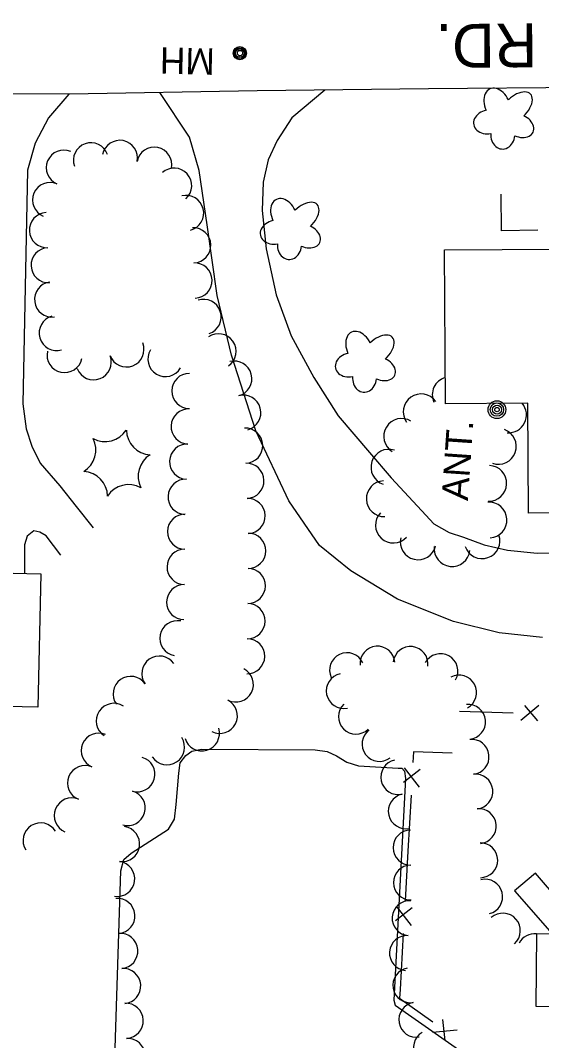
# Model space of a CAD drawing. Extents: x 189384 to 193282, y 256970 to 260388.
# Drawn here: x 190703.8 to 190822.4, y 259634.9 to 259866.8 of the extents above; entities that cross this region are included whole.
import ezdxf

# ---------------------------------------------------------------- set-up
doc = ezdxf.new("R2010")
doc.units = 0
for name, color, linetype in [('E_DRN_Grate', 7, 'Continuous'), ('E_DWY', 7, 'Continuous'), ('E_LAND_Vegetation', 7, 'Continuous'), ('E_MISCPROP', 7, 'Continuous'), ('E_MISCPROP_HvyDash', 7, 'Continuous'), ('E_MISCPROP_HvyLine', 7, 'Continuous'), ('E_MISCPROP_Railing', 7, 'Continuous'), ('E_RDWY', 7, 'Continuous'), ('E_RDWY_Name', 7, 'Continuous')]:
    doc.layers.add(name, color=color, linetype=linetype)

# ---------------------------------------------------------------- blocks, each defined once
blk = doc.blocks.new('MHO_6')
at = {"layer": 'E_DRN_Grate'}
for centre, radius in [((0.04, -0.06), 1.5), ((0.04, -0.06), 1.22), ((0.04, -0.07), 0.968), ((0.01, -0.08), 0.605)]:
    blk.add_circle(centre, radius, dxfattribs=at)
blk = doc.blocks.new('MHT_4')
at = {"layer": 'E_DRN_Grate'}
blk.add_text('MH', height=6, rotation=0, dxfattribs=at).set_placement((-5.61, -3.06))
blk = doc.blocks.new('POLE_3')
at = {"layer": 'E_MISCPROP'}
for centre, radius in [((-0.01, 0.02), 2.02), ((-0.01, 0.03), 1.52), ((0, -0.01), 1.01), ((0, 0), 0.502)]:
    blk.add_circle(centre, radius, dxfattribs=at)
blk = doc.blocks.new('ANT_2')
at = {"layer": 'E_MISCPROP'}
blk.add_text('ANT.', height=6, rotation=360, dxfattribs=at).set_placement((0.55, -0.39))
blk = doc.blocks.new('PINEL')
at = {"layer": 'E_LAND_Vegetation'}
for centre, start, end in [((-8.23, 7.26), 275.2112, 0.9761), ((2.17, 10.66), 215.2112, 300.9761), ((10.31, 3.35), 155.2112, 240.9761), ((-10.49, -3.45), 335.2112, 60.9761), ((8.05, -7.36), 95.2112, 180.9761), ((-2.35, -10.75), 35.2112, 120.9761)]:
    blk.add_arc(centre, 5.72, start, end, dxfattribs=at)
blk = doc.blocks.new('TREE')
at = {"layer": 'E_LAND_Vegetation'}
for centre, major_axis, ratio in [((-1.07, 3.38), (0.91, -3.32), 0.782863), ((2.88, 1.66), (-3.52, -1.95), 0.691916), ((-3.74, -0.07), (3.29, -0.08), 0.832022), ((2.54, -2.64), (-3.34, 3.06), 0.560249), ((-1.48, -3.66), (1.2, 3.24), 0.716896)]:
    blk.add_ellipse(centre, major_axis=major_axis, ratio=ratio, start_param=1.570796, end_param=4.712389, dxfattribs=at)

msp = doc.modelspace()

# ---------------------------------------------------------------- linework, layer by layer
at = {"layer": 'E_DWY'}
for points in [[(190714.86, 259850.07), (190710.22, 259844.68), (190707.14, 259838.94), (190705.46, 259832.74), (190704.36, 259779.68), (190705.13, 259773.97), (190706.42, 259770.05), (190708.29, 259766.17), (190712.77, 259760.97), (190716.53, 259756.29), (190720.4, 259751.42)], [(190822.67, 259726.51), (190812.77, 259727.59), (190802.36, 259730.18), (190789.63, 259735.25), (190779, 259741.66), (190771.88, 259747.4), (190764.87, 259757.58), (190757.37, 259773.48), (190751.88, 259790.71), (190748.62, 259804.27), (190746.3, 259820.32), (190744.49, 259832.67), (190742.31, 259840.27), (190735.54, 259850.42)], [(190773.11, 259850.97), (190765.59, 259844.64), (190762.27, 259839.55), (190760.24, 259835.15), (190759.04, 259830.05), (190758.81, 259823.59), (190759.74, 259814.92), (190762.06, 259804.45), (190765.45, 259795.12), (190770.57, 259785.65), (190776.12, 259776.89), (190783.26, 259768.55), (190788.17, 259762.81), (190795.15, 259755.33), (190797.89, 259752.39), (190801.43, 259750.38), (190804.69, 259749.31), (190809.35, 259747.59), (190814.65, 259746.4), (190821.43, 259745.72), (190834.6, 259745.78)], [(190713.04, 259745.23), (190709.68, 259749.65), (190708.27, 259750.49), (190706.9, 259750.76), (190705.36, 259749.58), (190704.76, 259747.6), (190704.71, 259741.1)], [(190725.28, 259630.81), (190726.64, 259673.45), (190727.36, 259676.06), (190728.99, 259677.51), (190737.49, 259682.96), (190738.9, 259685.19), (190739.27, 259688.57), (190739.84, 259695.68), (190740.15, 259698.04), (190741.46, 259699.68), (190742.84, 259700.67), (190745.05, 259701.15), (190770.92, 259701), (190773.65, 259700.58), (190775.77, 259699.59), (190778.08, 259698.18), (190780.77, 259697.32), (190789.78, 259696.77), (190790.65, 259696.77), (190791.22, 259696.09), (190791.43, 259694.43), (190788.77, 259644.03), (190789.08, 259642.89), (190819.96, 259621.32)]]:
    msp.add_lwpolyline(points, dxfattribs=at)
at = {"layer": 'E_LAND_Vegetation'}
for centre, radius, start, end in [((190713.69, 259833.34), 4, 67.007, 246.9917), ((190719.86, 259835.01), 4, 19.509, 199.4937), ((190726.44, 259835.56), 4, 348.7183, 168.703), ((190734.29, 259833.99), 4, 348.7183, 168.703), ((190738.8, 259829.24), 4, 312.0189, 132.0036), ((190710.57, 259825.98), 4, 67.007, 246.9917), ((190741.54, 259823.03), 4, 284.298, 104.2826), ((190709.86, 259819.14), 4, 92.8579, 272.8425), ((190743.16, 259815.68), 4, 272.1039, 92.0886), ((190710.25, 259811.15), 4, 92.8579, 272.8425), ((190743.45, 259807.68), 4, 272.1039, 92.0886), ((190711.04, 259803.36), 4, 97.325, 277.3097), ((190745.51, 259799.4), 4, 288.5413, 108.526), ((190712.09, 259795.76), 4, 106.1392, 286.1239), ((190748.91, 259791.58), 4, 304.8154, 124.8001), ((190727.94, 259792.02), 4, 201.3898, 21.3745), ((190713.87, 259790.76), 4, 167.9757, 347.9603), ((190736.82, 259789.85), 4, 149.1247, 329.1094), ((190720.49, 259789.1), 4, 201.3898, 21.3745), ((190752.5, 259785.37), 4, 284.7594, 104.7441), ((190742.26, 259782.56), 4, 89.4755, 269.4602), ((190801.63, 259781.71), 4.07, 106.243, 203.9106), ((190754.54, 259777.63), 4, 284.7594, 104.7441), ((190795.02, 259777.82), 4.07, 35.2422, 215.2269), ((190814.92, 259777.14), 4.07, 265.7473, 40.4027), ((190742.11, 259774.49), 4, 87.5068, 267.4915), ((190790.58, 259772.24), 4.07, 58.531, 238.5157), ((190754.97, 259770.13), 4, 271.9978, 91.9825), ((190812.6, 259769.96), 4.07, 250.5561, 70.5407), ((190741.76, 259766.5), 4, 87.5068, 267.4915), ((190787.67, 259765.24), 4.07, 71.9601, 251.9448), ((190755.25, 259762.14), 4, 271.9978, 91.9825), ((190810.41, 259761.56), 4.07, 267.5573, 87.542), ((190741.41, 259758.5), 4, 87.5068, 267.4915), ((190786.62, 259758.06), 4.07, 92.2877, 272.2724), ((190755.53, 259754.14), 4, 271.9978, 91.9825), ((190810.47, 259753.22), 4.07, 273.5045, 93.4892), ((190741.28, 259750.57), 4, 89.3282, 269.3129), ((190788.71, 259752.08), 4.07, 137.0153, 317), ((190755.66, 259746.24), 4, 269.4451, 89.4298), ((190794.35, 259748.26), 4.07, 166.6956, 346.6803), ((190808.89, 259748.52), 4.07, 199.1129, 19.0976), ((190802.06, 259746.72), 4.07, 173.5239, 353.5086), ((190741.18, 259742.57), 4, 89.3282, 269.3129), ((190755.58, 259738.24), 4, 269.4451, 89.4298), ((190741.09, 259734.57), 4, 89.3282, 269.3129), ((190755.5, 259730.24), 4, 269.4451, 89.4298), ((190739.55, 259726.34), 4, 79.0518, 259.0364), ((190755.42, 259722.24), 4, 269.4451, 89.4298), ((190785.08, 259720.57), 3.97, 4.8269, 184.8115), ((190792.6, 259720.49), 3.97, 353.2953, 173.2799), ((190735.45, 259718.3), 4, 35.295, 215.2797), ((190778.15, 259719.08), 3.97, 25.1576, 205.1423), ((190799.41, 259718.86), 3.97, 330.7842, 150.7689), ((190752.84, 259715.84), 4, 243.0063, 62.991), ((190728.92, 259713.68), 4, 35.295, 215.2797), ((190777.4, 259714.36), 3.97, 101.9581, 281.9428), ((190803.68, 259714), 3.97, 298.2652, 118.2498), ((190749.21, 259708.71), 4, 243.0063, 62.991), ((190725.08, 259707.55), 4, 56.837, 236.8217), ((190780.18, 259708.51), 3.97, 134.2601, 314.2448), ((190805.71, 259707.33), 3.97, 275.5855, 95.5702), ((190745.11, 259704.71), 4, 196.8082, 16.7929), ((190785.55, 259702.32), 3.97, 127.181, 307.1657), ((190721.65, 259700.78), 4, 67.1882, 247.1729), ((190737.18, 259701.58), 4, 213.0132, 32.9978), ((190806.51, 259699.4), 3.97, 276.2135, 96.1982), ((190730.44, 259695.42), 4, 253.908, 73.8926), ((190789.81, 259694.76), 3.97, 102.3955, 282.3802), ((190718.55, 259693.41), 4, 67.1882, 247.1729), ((190807.36, 259691.5), 3.97, 276.2135, 96.1982), ((190728.22, 259687.74), 4, 253.908, 73.8926), ((190715.49, 259686.03), 4, 67.4818, 247.4664), ((190791.52, 259687), 3.97, 102.3955, 282.3802), ((190808.15, 259683.62), 3.97, 275.5953, 95.58), ((190708.41, 259680.36), 4, 32.3111, 212.2958), ((190726.96, 259679.55), 4, 261.8375, 81.8222), ((190792.61, 259678.75), 3.97, 90.6728, 270.6575), ((190808.47, 259675.87), 3.97, 270.5674, 90.5521), ((190725.83, 259671.63), 4, 261.8375, 81.8222), ((190792.7, 259670.8), 3.97, 90.6728, 270.6575), ((190809.58, 259667.57), 3.97, 284.1445, 104.1292), ((190725.87, 259663.2), 4, 274.8332, 94.8179), ((190792.39, 259662.69), 3.97, 85.7021, 265.6868), ((190813.63, 259659.86), 3.97, 311.6972, 131.6819), ((190726.54, 259655.23), 4, 274.8332, 94.8179), ((190791.79, 259654.77), 3.97, 85.7021, 265.6868), ((190820.85, 259655.19), 3.97, 83.4113, 152.8171), ((190727.21, 259647.26), 4, 274.8332, 94.8179), ((190792.55, 259647.43), 3.97, 99.891, 279.8757), ((190727.78, 259639.35), 4, 273.0708, 93.0555), ((190793.92, 259639.6), 3.97, 99.891, 279.8757), ((190797.24, 259633.29), 3.97, 120.5768, 300.5615), ((190728.21, 259631.36), 4, 273.0708, 93.0555)]:
    msp.add_arc(centre, radius, start, end, dxfattribs=at)
at = {"layer": 'E_MISCPROP_HvyDash'}
msp.add_lwpolyline([(190860.83, 259670.2), (190855.55, 259670.28), (190855.24, 259665.71), (190850.38, 259665.78), (190850.43, 259666.79), (190835.72, 259667.12), (190835.62, 259666.24), (190826.6, 259666.48), (190821.03, 259672.91), (190816.25, 259668.93), (190824.87, 259659.11)], dxfattribs=at)
at = {"layer": 'E_MISCPROP_HvyLine'}
for points in [[(190800.34, 259814.66), (190852.83, 259814.94), (190852.83, 259814.94), (190852.96, 259789.91), (190852.96, 259789.91), (190842.55, 259789.86), (190842.55, 259789.86), (190842.74, 259754.93), (190842.74, 259754.93), (190842.74, 259754.93), (190819.44, 259754.81), (190819.44, 259754.81), (190819.31, 259779.78), (190819.31, 259779.78), (190800.53, 259779.68), (190800.34, 259814.66)], [(190708.48, 259741.02), (190708.48, 259741.02), (190707.8, 259710.68), (190707.8, 259710.68), (190679.36, 259711.31), (190680.04, 259741.65), (190680.04, 259741.65), (190708.48, 259741.02)], [(190839.24, 259658.98), (190839.24, 259658.98), (190821.31, 259659.14), (190821.31, 259659.14), (190821.16, 259642.72), (190839.09, 259642.56), (190839.09, 259642.56), (190839.24, 259658.98)]]:
    msp.add_lwpolyline(points, close=True, dxfattribs=at)
at = {"layer": 'E_MISCPROP_Railing'}
for p, q in [((190821.84, 259711.02), (190817.73, 259707.65)), ((190821.55, 259707.53), (190818.64, 259711.05)), ((190794.77, 259696.51), (190791.01, 259693.56)), ((190791.13, 259696.91), (190794.54, 259692.51)), ((190792.98, 259665.06), (190789.22, 259662.1)), ((190789.34, 259665.46), (190792.76, 259661.05)), ((190799.91, 259639.64), (190800.43, 259634.89)), ((190797.64, 259636.76), (190803.19, 259637.33))]:
    msp.add_line(p, q, dxfattribs=at)
for points in [[(190821.6, 259819.11), (190813.28, 259819), (190813.22, 259827.35)], [(190815.94, 259709.33), (190803.73, 259709.71)], [(190802.11, 259700.23), (190793.3, 259700.55), (190793.16, 259698.11)], [(190792.74, 259690.68), (190792.01, 259677.9)], [(190792.01, 259677.9), (190791.38, 259666.65)], [(190790.95, 259659.22), (190790.23, 259646.44)], [(190790.23, 259646.44), (190790.11, 259644.47), (190797.7, 259639.12)]]:
    msp.add_lwpolyline(points, dxfattribs=at)
at = {"layer": 'E_RDWY'}
msp.add_lwpolyline([(190977.43, 259841.11), (190974.92, 259843.83), (190971.99, 259845.42), (190966.37, 259847.83), (190958.04, 259850.14), (190948.14, 259851.49), (190933.02, 259852), (190911.04, 259852.07), (190866.77, 259851.65), (190832.26, 259851.54), (190796.71, 259851.25), (190757.73, 259850.8), (190715.01, 259850.07), (190672.84, 259850.18), (190636.69, 259849.75), (190613, 259849.81), (190612.43, 259849.8)], dxfattribs=at)

# ---------------------------------------------------------------- block references
at = {"layer": 'E_DRN_Grate'}
for name, p, rotation in [('MHT_4', (190742.44, 259857.5), 178.66600446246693), ('MHO_6', (190753.8, 259859.33), 178.66600426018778)]:
    msp.add_blockref(name, p, dxfattribs=dict(at, rotation=rotation))
at = {"layer": 'E_LAND_Vegetation'}
for name, p, rotation in [('TREE', (190813.81, 259844.6), 86.0329774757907), ('TREE', (190765.26, 259819.49), 86.0329783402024), ('TREE', (190782.34, 259789.31), 86.0329780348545), ('PINEL', (190725.75, 259766.26), 86.0329790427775)]:
    msp.add_blockref(name, p, dxfattribs=dict(at, rotation=rotation))
at = {"layer": 'E_MISCPROP', "xscale": 0.9999982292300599, "yscale": 0.9999982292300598, "rotation": 84.20842447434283}
msp.add_blockref('POLE_3', (190812.29, 259778.33), dxfattribs=at)
at = {"layer": 'E_MISCPROP', "rotation": 86.0329776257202}
msp.add_blockref('ANT_2', (190805.23, 259756.99), dxfattribs=at)

# ---------------------------------------------------------------- texts
at = {"layer": 'E_RDWY_Name'}
msp.add_text('LEMMA CRK RD.', height=10, rotation=180.4711, dxfattribs=at).set_placement((190904.58, 259866.84))

doc.saveas('drawing.dxf')
